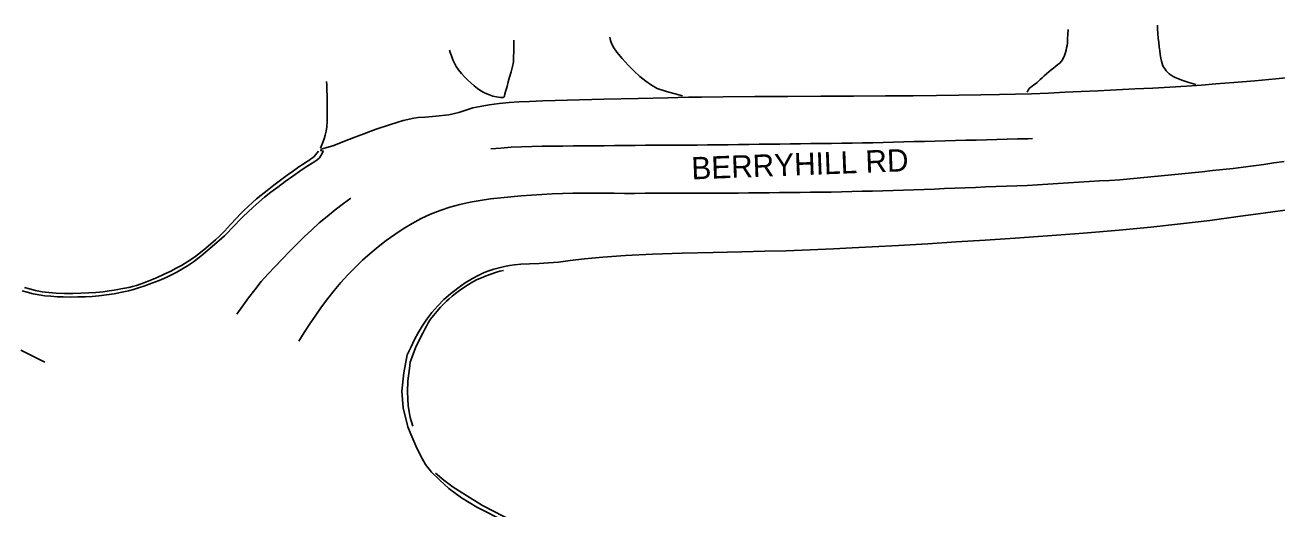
# Model space of a CAD drawing. Extents: x 1961683 to 1977751, y 798292 to 805767.
# Drawn here: x 1962697.7 to 1963000.6, y 800071.4 to 800188.4 of the extents above; entities that cross this region are included whole.
import ezdxf

# ---------------------------------------------------------------- set-up
doc = ezdxf.new("R2010")
doc.units = 0
for name, color, linetype in [('RD_EX_Road', 7, 'Continuous'), ('RD_EX_Road_Paint', 7, 'Continuous'), ('RD_TX_RoadID', 7, 'Continuous')]:
    doc.layers.add(name, color=color, linetype=linetype)

msp = doc.modelspace()

# ---------------------------------------------------------------- linework, layer by layer
at = {"layer": 'RD_EX_Road'}
for points in [[(1962950.08, 800187.37), (1962950.04, 800186.32), (1962949.97, 800185.01), (1962949.91, 800184.15), (1962949.83, 800183.53), (1962949.73, 800182.94), (1962949.62, 800182.37), (1962949.48, 800181.84), (1962949.32, 800181.33), (1962949.14, 800180.86), (1962948.93, 800180.43), (1962948.7, 800180.03), (1962948.42, 800179.64), (1962948.07, 800179.25), (1962947.64, 800178.86), (1962947.14, 800178.46), (1962946.59, 800178.05), (1962946.03, 800177.61), (1962945.46, 800177.14), (1962944.87, 800176.64), (1962944.31, 800176.14), (1962943.8, 800175.69), (1962943.36, 800175.27), (1962942.97, 800174.89), (1962942.6, 800174.55), (1962942.22, 800174.23), (1962941.83, 800173.95), (1962941.43, 800173.69), (1962941.04, 800173.42), (1962940.71, 800173.08), (1962940.44, 800172.67), (1962940.21, 800172.19)], [(1962971.72, 800188.45), (1962971.76, 800187.56), (1962971.84, 800186.42), (1962971.92, 800185.3), (1962972.02, 800184.22), (1962972.13, 800183.19), (1962972.25, 800182.22), (1962972.38, 800181.3), (1962972.52, 800180.46), (1962972.68, 800179.74), (1962972.86, 800179.12), (1962973.05, 800178.6), (1962973.28, 800178.16), (1962973.54, 800177.74), (1962973.84, 800177.35), (1962974.19, 800176.98), (1962974.58, 800176.64), (1962975.01, 800176.32), (1962975.5, 800176.02), (1962976.04, 800175.74), (1962976.78, 800175.43), (1962977.85, 800175.04), (1962979.27, 800174.58), (1962981.02, 800174.04)], [(1962815.94, 800184.78), (1962815.95, 800182.25), (1962815.93, 800180.53), (1962815.87, 800179.53), (1962815.66, 800178.41), (1962815.32, 800177.09), (1962814.97, 800175.84), (1962814.64, 800174.7), (1962814.33, 800173.61), (1962814.05, 800172.59), (1962813.84, 800171.8), (1962813.7, 800171.26), (1962813.63, 800171.08), (1962813.56, 800170.96), (1962813.47, 800170.91), (1962813.33, 800170.9), (1962812.74, 800170.93), (1962811.8, 800171.06), (1962810.91, 800171.25), (1962810.13, 800171.52), (1962809.41, 800171.8), (1962808.74, 800172.12), (1962808.01, 800172.56), (1962807.21, 800173.12), (1962806.4, 800173.74), (1962805.6, 800174.43), (1962804.82, 800175.14), (1962804.06, 800175.88), (1962803.32, 800176.7), (1962802.62, 800177.58), (1962802.05, 800178.41), (1962801.62, 800179.21), (1962801.22, 800180.06), (1962800.86, 800180.96), (1962800.58, 800181.81), (1962800.44, 800182.39)], [(1962839.19, 800185.54), (1962839.38, 800184.72), (1962839.71, 800183.79), (1962840.16, 800182.92), (1962840.93, 800181.86), (1962842.19, 800180.36), (1962843.67, 800178.73), (1962845.1, 800177.29), (1962846.5, 800176.01), (1962847.91, 800174.87), (1962849.31, 800173.91), (1962850.68, 800173.12), (1962852.89, 800172.33), (1962856.82, 800171.31)], [(1962697, 800124.15), (1962698.26, 800123.78), (1962699.69, 800123.41), (1962701.09, 800123.14), (1962702.5, 800122.95), (1962703.97, 800122.81), (1962705.47, 800122.72), (1962706.96, 800122.66), (1962708.59, 800122.64), (1962710.48, 800122.67), (1962712.37, 800122.72), (1962713.96, 800122.79), (1962715.54, 800122.92), (1962717.38, 800123.14), (1962719.3, 800123.44), (1962721.13, 800123.78), (1962722.73, 800124.13), (1962723.97, 800124.46), (1962725.18, 800124.84), (1962726.7, 800125.35), (1962728.4, 800125.97), (1962730.18, 800126.66), (1962731.83, 800127.36), (1962733.18, 800128.01), (1962734.4, 800128.65), (1962735.66, 800129.36), (1962737.01, 800130.19), (1962738.46, 800131.19), (1962740.24, 800132.54), (1962742.54, 800134.45), (1962744.68, 800136.29), (1962745.93, 800137.43), (1962746.78, 800138.28), (1962747.69, 800139.24), (1962748.61, 800140.22), (1962749.5, 800141.15), (1962750.46, 800142.11), (1962751.6, 800143.2), (1962752.88, 800144.37), (1962754.24, 800145.58), (1962755.68, 800146.8), (1962757.21, 800148), (1962758.86, 800149.24), (1962760.67, 800150.58), (1962762.5, 800151.9), (1962764.19, 800153.09), (1962765.74, 800154.14), (1962767.15, 800155.03), (1962768.28, 800155.74), (1962768.95, 800156.33), (1962769.22, 800156.73), (1962769.62, 800157.4), (1962769.83, 800157.94), (1962769.29, 800158.05), (1962769.39, 800158.43), (1962770.49, 800158.71), (1962772.41, 800159.32), (1962775.42, 800160.5), (1962779, 800161.92), (1962782.65, 800163.24), (1962786.13, 800164.4), (1962789.24, 800165.34), (1962791.82, 800165.95), (1962792.86, 800166.1), (1962794.61, 800166.17), (1962797.08, 800166.37), (1962800.23, 800166.76), (1962802.68, 800167.28), (1962804.35, 800167.88), (1962806.02, 800168.38), (1962807.87, 800168.77), (1962810.02, 800169.11), (1962812.44, 800169.43), (1962814.85, 800169.67), (1962817.21, 800169.83), (1962819.78, 800169.97), (1962822.96, 800170.1), (1962828.99, 800170.28), (1962837.73, 800170.5), (1962846.05, 800170.7), (1962853.25, 800170.87), (1962858.21, 800170.97), (1962861.38, 800171.01), (1962866.64, 800171.06), (1962874.3, 800171.12), (1962882.28, 800171.17), (1962890.23, 800171.2), (1962898.18, 800171.25), (1962905.95, 800171.3), (1962912.64, 800171.34), (1962918.24, 800171.37), (1962923.67, 800171.44), (1962928.96, 800171.56), (1962933.5, 800171.65), (1962937.33, 800171.71), (1962941.27, 800171.83), (1962945.39, 800172), (1962949.37, 800172.17), (1962953.22, 800172.35), (1962957.37, 800172.56), (1962961.84, 800172.78), (1962966.27, 800172.99), (1962970.57, 800173.2), (1962974.73, 800173.42), (1962978.71, 800173.65), (1962982.39, 800173.91), (1962985.88, 800174.19), (1962990.19, 800174.54), (1962995.31, 800174.95), (1963000.35, 800175.41), (1963005.22, 800175.93)], [(1962769.18, 800158.62), (1962769.7, 800159.86), (1962770.07, 800160.88), (1962770.34, 800161.8), (1962770.56, 800162.74), (1962770.72, 800163.8), (1962770.8, 800165.12), (1962770.83, 800166.54), (1962770.84, 800167.95), (1962770.8, 800170.14), (1962770.71, 800173.92), (1962770.69, 800174.77)], [(1962768.68, 800157.95), (1962768.38, 800157.5), (1962768.01, 800157.02), (1962767.65, 800156.63), (1962767.24, 800156.28), (1962766.81, 800155.96), (1962766.35, 800155.66), (1962765.78, 800155.31), (1962765, 800154.81), (1962763.96, 800154.12), (1962762.63, 800153.19), (1962761.11, 800152.1), (1962759.5, 800150.93), (1962757.87, 800149.7), (1962756.27, 800148.45), (1962754.84, 800147.31), (1962753.75, 800146.39), (1962752.78, 800145.52), (1962751.7, 800144.52), (1962750.67, 800143.55), (1962749.86, 800142.74), (1962748.9, 800141.73), (1962747.45, 800140.18), (1962745.93, 800138.57), (1962744.78, 800137.4), (1962743.77, 800136.44), (1962742.68, 800135.48), (1962741.48, 800134.48), (1962740.14, 800133.41), (1962738.68, 800132.31), (1962737.11, 800131.24), (1962735.59, 800130.3), (1962734.31, 800129.58), (1962732.99, 800128.91), (1962731.36, 800128.13), (1962729.7, 800127.36), (1962728.31, 800126.77), (1962727.06, 800126.28), (1962725.82, 800125.82), (1962724.68, 800125.44), (1962723.72, 800125.16), (1962722.82, 800124.96), (1962721.86, 800124.77), (1962720.92, 800124.61), (1962720.13, 800124.46), (1962719.24, 800124.31), (1962718.05, 800124.12), (1962716.58, 800123.92), (1962714.87, 800123.75), (1962713.04, 800123.62), (1962711.21, 800123.54), (1962709.31, 800123.51), (1962707.26, 800123.52), (1962705.25, 800123.59), (1962703.47, 800123.72), (1962701.83, 800123.93), (1962700.26, 800124.25), (1962698.82, 800124.62), (1962697.57, 800124.97)], [(1962814.05, 800068.28), (1962807.05, 800071.81), (1962803.32, 800074.01), (1962800.23, 800076.27), (1962798.07, 800078.3), (1962796.08, 800080.28), (1962794.62, 800082.1), (1962793.5, 800084.09), (1962792.25, 800086.61), (1962791.03, 800089.42), (1962790.35, 800091.23), (1962789.24, 800095.86), (1962788.89, 800099.85), (1962789.33, 800104.32), (1962790.18, 800108.61), (1962791.14, 800110.6), (1962791.98, 800112.34), (1962792.81, 800113.95), (1962793.78, 800115.59), (1962794.89, 800117.25), (1962796.17, 800118.93), (1962797.57, 800120.54), (1962799.05, 800122.03), (1962800.64, 800123.44), (1962802.4, 800124.81), (1962804.21, 800126.07), (1962805.95, 800127.11), (1962807.52, 800127.93), (1962808.8, 800128.53), (1962809.95, 800128.98), (1962811.16, 800129.37), (1962812.41, 800129.71), (1962813.69, 800130), (1962814.96, 800130.25), (1962816.16, 800130.46), (1962817.64, 800130.6), (1962819.73, 800130.7), (1962822.09, 800130.78), (1962824.37, 800130.89), (1962826.79, 800131.1), (1962829.58, 800131.45), (1962833.04, 800131.87), (1962837.5, 800132.27), (1962842.99, 800132.65), (1962849.52, 800132.97), (1962856.73, 800133.23), (1962864.23, 800133.44), (1962871.18, 800133.6), (1962876.72, 800133.71), (1962881.89, 800133.84), (1962887.68, 800134.05), (1962893.29, 800134.28), (1962897.87, 800134.51), (1962902.71, 800134.78), (1962909.09, 800135.13), (1962916.15, 800135.54), (1962923.03, 800135.98), (1962929.99, 800136.43), (1962937.28, 800136.91), (1962945.14, 800137.45), (1962953.82, 800138.11), (1962962.44, 800138.83), (1962970.13, 800139.54), (1962977.31, 800140.31), (1962984.38, 800141.19), (1962991.27, 800142.11), (1962997.89, 800143), (1963004.37, 800143.91)], [(1962791.54, 800091.36), (1962790.87, 800093.45), (1962790.43, 800096.27), (1962790.23, 800099.73), (1962790.32, 800102.36), (1962790.7, 800105.37), (1962790.92, 800106.86), (1962791.37, 800108.18), (1962792.19, 800110.35), (1962793.13, 800112.33), (1962793.96, 800113.9), (1962794.47, 800114.88), (1962794.84, 800115.6), (1962795.27, 800116.39), (1962795.82, 800117.25), (1962796.52, 800118.19), (1962797.33, 800119.16), (1962798.23, 800120.15), (1962799.07, 800121.02), (1962799.72, 800121.67), (1962800.33, 800122.23), (1962801.04, 800122.83), (1962801.87, 800123.49), (1962802.85, 800124.22), (1962803.91, 800124.97), (1962804.99, 800125.69), (1962806.06, 800126.34), (1962807.11, 800126.85), (1962808.16, 800127.3), (1962809.26, 800127.75), (1962810.39, 800128.18), (1962811.53, 800128.56), (1962812.59, 800128.86), (1962813.49, 800129.08)], [(1962877.83, 800039.22), (1962872.12, 800040.88), (1962868.46, 800042.08), (1962861.54, 800044.5), (1962860.68, 800044.81), (1962856.76, 800046.76), (1962849.6, 800050.61), (1962839.92, 800055.71), (1962830.45, 800060.61), (1962813.52, 800069.52), (1962808.41, 800072.22), (1962804.11, 800074.84), (1962801.29, 800076.63), (1962799.04, 800078.32), (1962797.02, 800080.03)]]:
    msp.add_lwpolyline(points, dxfattribs=at)
at = {"layer": 'RD_EX_Road_Paint'}
for points in [[(1962810.38, 800158.49), (1962812.87, 800158.68), (1962815.37, 800158.86), (1962817.86, 800158.98), (1962820.36, 800159.06), (1962822.86, 800159.11), (1962825.36, 800159.13), (1962827.86, 800159.16), (1962830.36, 800159.18), (1962832.86, 800159.2), (1962835.36, 800159.23), (1962837.86, 800159.25), (1962840.36, 800159.27), (1962842.86, 800159.29), (1962845.36, 800159.32), (1962847.86, 800159.34), (1962850.36, 800159.36), (1962852.86, 800159.38), (1962855.36, 800159.39), (1962857.86, 800159.4), (1962860.36, 800159.41), (1962862.86, 800159.43), (1962865.36, 800159.46), (1962867.86, 800159.5), (1962870.36, 800159.53), (1962872.85, 800159.56), (1962875.35, 800159.59), (1962877.85, 800159.63), (1962880.35, 800159.66), (1962882.85, 800159.69), (1962885.35, 800159.73), (1962887.85, 800159.76), (1962890.35, 800159.79), (1962892.85, 800159.82), (1962895.35, 800159.86), (1962897.85, 800159.89), (1962900.35, 800159.92), (1962902.85, 800159.96), (1962905.35, 800160.03), (1962907.84, 800160.09), (1962910.34, 800160.16), (1962912.84, 800160.23), (1962915.34, 800160.29), (1962917.84, 800160.36), (1962920.34, 800160.42), (1962922.84, 800160.49), (1962925.33, 800160.55), (1962927.83, 800160.62), (1962930.33, 800160.69), (1962932.83, 800160.75), (1962935.33, 800160.82), (1962937.83, 800160.88), (1962940.33, 800160.95), (1962941.49, 800160.98)], [(1962763.92, 800111.94), (1962765.28, 800114.04), (1962766.62, 800116.15), (1962768.03, 800118.22), (1962769.47, 800120.26), (1962770.94, 800122.28), (1962772.52, 800124.22), (1962774.09, 800126.16), (1962775.79, 800128), (1962777.57, 800129.76), (1962779.34, 800131.52), (1962781.2, 800133.19), (1962783.15, 800134.76), (1962785.1, 800136.32), (1962787.15, 800137.75), (1962789.21, 800139.17), (1962791.35, 800140.45), (1962793.54, 800141.67), (1962795.81, 800142.72), (1962798.16, 800143.57), (1962800.53, 800144.34), (1962802.95, 800145), (1962805.38, 800145.58), (1962807.84, 800145.99), (1962810.31, 800146.37), (1962812.8, 800146.63), (1962815.29, 800146.88), (1962817.77, 800147.13), (1962820.27, 800147.28), (1962822.76, 800147.43), (1962825.26, 800147.58), (1962827.76, 800147.71), (1962830.26, 800147.74), (1962832.76, 800147.74), (1962835.26, 800147.73), (1962837.76, 800147.73), (1962840.26, 800147.73), (1962842.76, 800147.72), (1962845.26, 800147.72), (1962847.76, 800147.73), (1962850.25, 800147.74), (1962852.75, 800147.74), (1962855.25, 800147.75), (1962857.75, 800147.76), (1962860.25, 800147.76), (1962862.75, 800147.77), (1962865.25, 800147.77), (1962867.75, 800147.78), (1962870.25, 800147.79), (1962872.75, 800147.82), (1962875.25, 800147.84), (1962877.75, 800147.87), (1962880.25, 800147.9), (1962882.75, 800147.92), (1962885.25, 800147.95), (1962887.75, 800147.98), (1962890.25, 800148.01), (1962892.74, 800148.03), (1962895.24, 800148.07), (1962897.74, 800148.14), (1962900.24, 800148.21), (1962902.74, 800148.29), (1962905.24, 800148.37), (1962907.73, 800148.44), (1962910.23, 800148.52), (1962912.73, 800148.6), (1962915.23, 800148.68), (1962917.73, 800148.77), (1962920.22, 800148.87), (1962922.72, 800148.97), (1962925.22, 800149.07), (1962927.71, 800149.17), (1962930.21, 800149.27), (1962932.71, 800149.37), (1962935.2, 800149.47), (1962937.7, 800149.56), (1962940.2, 800149.66), (1962942.69, 800149.78), (1962945.19, 800149.93), (1962947.68, 800150.09), (1962950.18, 800150.24), (1962952.67, 800150.4), (1962955.17, 800150.55), (1962957.66, 800150.71), (1962960.15, 800150.86), (1962962.65, 800151.03), (1962965.14, 800151.25), (1962967.62, 800151.49), (1962970.11, 800151.73), (1962972.6, 800151.96), (1962975.09, 800152.2), (1962977.58, 800152.44), (1962980.06, 800152.68), (1962982.55, 800152.95), (1962985.03, 800153.22), (1962987.52, 800153.49), (1962990, 800153.76), (1962992.49, 800154.03), (1962994.97, 800154.36), (1962997.44, 800154.72), (1962999.91, 800155.08), (1963002.39, 800155.44)], [(1962748.93, 800118.52), (1962751.77, 800122.43), (1962753.31, 800124.4), (1962754.84, 800126.37), (1962756.53, 800128.21), (1962758.22, 800130.06), (1962759.97, 800131.84), (1962761.72, 800133.63), (1962763.49, 800135.4), (1962765.25, 800137.17), (1962767.08, 800138.88), (1962768.91, 800140.58), (1962770.84, 800142.16), (1962772.78, 800143.75), (1962774.78, 800145.24), (1962776.56, 800146.56)], [(1962696.69, 800109.75), (1962698.93, 800108.64), (1962701.17, 800107.54), (1962702.46, 800106.9)]]:
    msp.add_lwpolyline(points, dxfattribs=at)

# ---------------------------------------------------------------- texts
at = {"layer": 'RD_TX_RoadID'}
msp.add_text('BERRYHILL RD', height=5.4, rotation=2.2068, dxfattribs=at).set_placement((1962859.04, 800151.08))

doc.saveas('drawing.dxf')
